// Mitsubishi GX Works2 project: 485编码器通讯程序   PLC: FX2N/FX2NC
// 485

PROGRAM MAIN
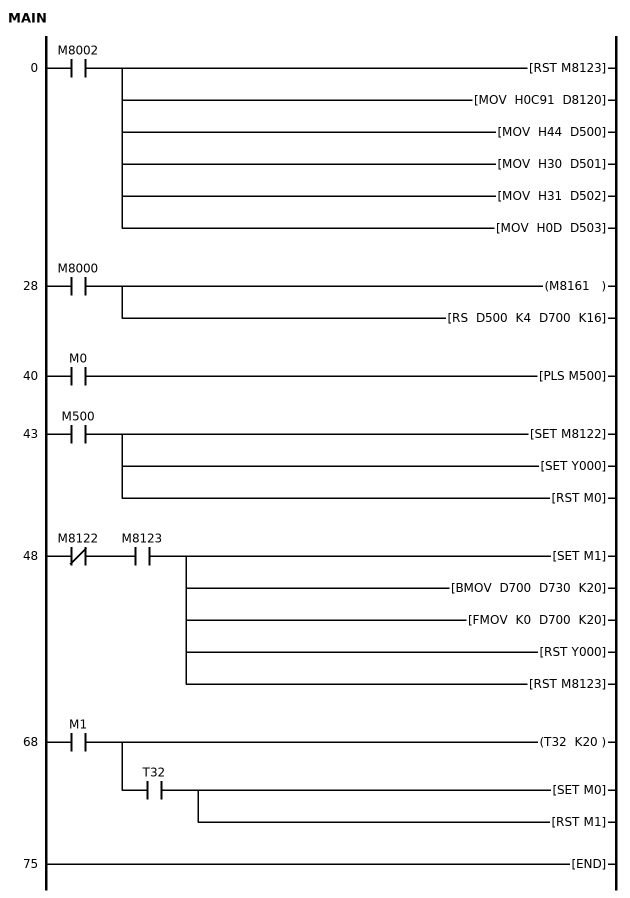
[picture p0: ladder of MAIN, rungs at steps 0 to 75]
0     LD      M8002
      RST     M8123
      MOV     H0C91 D8120
      MOV     H44 D500
      MOV     H30 D501
      MOV     H31 D502
      MOV     H0D D503
28    LD      M8000
      OUT     M8161
      RS      D500 K4 D700 K16
40    LD      M0
      PLS     M500
43    LD      M500
      SET     M8122
      SET     Y000
      RST     M0
48    LDI     M8122
      AND     M8123
      SET     M1
      BMOV    D700 D730 K20
      FMOV    K0 D700 K20
      RST     Y000
      RST     M8123
68    LD      M1
      OUT     T32 K20
      AND     T32
      SET     M0
      RST     M1
75    END
END_PROGRAM
